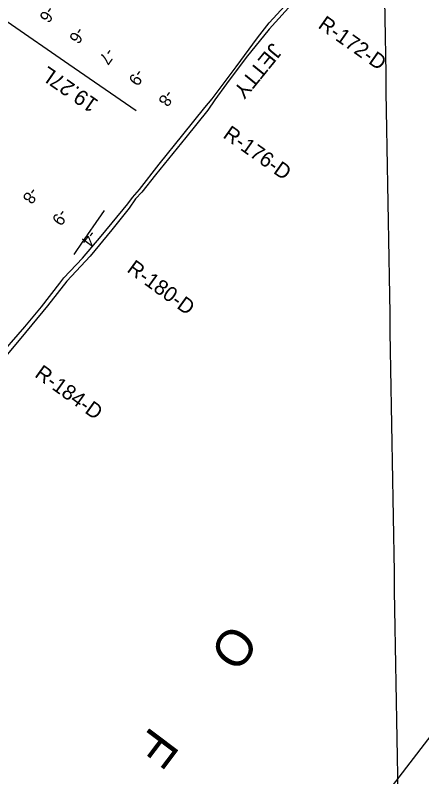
# Model space of a CAD drawing. Extents: x 3879599 to 3900814, y 146526 to 168888.
# Drawn here: x 3893070 to 3894188, y 154174 to 156266 of the extents above; entities that cross this region are included whole.
import ezdxf

# ---------------------------------------------------------------- set-up
doc = ezdxf.new("R2010")
doc.units = 0
for name, color, linetype in [('V-GRID-FRAM', 7, 'Continuous'), ('V-GRID-MAJR', 7, 'Continuous'), ('V-LEVE-TOET', 7, 'Continuous'), ('V-RIVR-IDEN', 7, 'Continuous'), ('V-RIVR-JETY', 7, 'Continuous'), ('V-RIVR-RANG', 7, 'Continuous'), ('V-RIVR-RANG-IDEN', 7, 'Continuous'), ('V-STRM-FMON', 7, 'Continuous'), ('V-TOPO-MINR', 7, 'Continuous')]:
    doc.layers.add(name, color=color, linetype=linetype)

msp = doc.modelspace()

# ---------------------------------------------------------------- linework, layer by layer
at = {"layer": 'V-GRID-FRAM'}
msp.add_lwpolyline([(3898776.6, 160226.4), (3889730.7, 148455.2), (3882888.9, 153284.4), (3891901.5, 165241.3), (3898776.6, 160226.4)], dxfattribs=at)
at = {"layer": 'V-GRID-MAJR'}
msp.add_spline([(3894134.7, 153416.7), (3894080.4, 156663.6), (3893979, 162723.9), (3893946.7, 164659.1)], degree=3, dxfattribs=at)
at = {"layer": 'V-LEVE-TOET'}
msp.add_lwpolyline([(3893403.2, 156002.9), (3893217.5, 156130.1), (3893048.4, 156247.9), (3892896.3, 156354.3)], dxfattribs=at)
at = {"layer": 'V-RIVR-JETY'}
for points in [[(3894117.3, 156651.7), (3894079.2, 156602.7), (3894043.1, 156551.8), (3894002.8, 156500.5), (3893956.5, 156444.6), (3893898.6, 156375.3), (3893839.2, 156305.5), (3893768.1, 156227.3), (3893705.7, 156149.9), (3893651.7, 156077.6), (3893618.9, 156033.2), (3893599.5, 156004.6)], [(3893611.6, 156035.8), (3893678, 156124.2), (3893736.5, 156203.8), (3893769, 156244.8), (3893811.6, 156291.5), (3893863.6, 156352.5), (3893892.8, 156383.2), (3893915.5, 156412.6), (3893955.9, 156461.3), (3894013.4, 156531), (3894060.3, 156596), (3894111.5, 156656.9), (3894119, 156666.1)], [(3893412.3, 155786.9), (3893466.4, 155856.6), (3893531.4, 155937.4), (3893591.8, 156012.4), (3893611.6, 156035.8)], [(3893599.5, 156004.6), (3893539.4, 155929.9), (3893455.8, 155827.2), (3893418.8, 155779.8), (3893401.2, 155761.7)], [(3893016.3, 155318.7), (3893097, 155409.6), (3893142.6, 155464.3), (3893193.3, 155529.8), (3893203.8, 155544.7), (3893255.4, 155598.4), (3893307, 155658.6), (3893380.2, 155747.8), (3893392.5, 155765), (3893412.3, 155786.9)], [(3893401.2, 155761.7), (3893383.4, 155735.7), (3893336, 155676), (3893276.6, 155604), (3893212.2, 155535.7), (3893158.9, 155467.2), (3893086, 155378.3), (3893009.8, 155289.4), (3892931, 155195.2), (3892859.8, 155101.4), (3892769.8, 154985), (3892723.9, 154932.9), (3892677.1, 154881.5), (3892656.9, 154860.4), (3892622.6, 154814.1), (3892534.6, 154695.5), (3892451.7, 154594.8), (3892385.6, 154513.6), (3892293.4, 154397.6), (3892219.9, 154301.1), (3892142.7, 154203.1), (3892063.5, 154110.7)]]:
    msp.add_lwpolyline(points, dxfattribs=at)
at = {"layer": 'V-TOPO-MINR'}
msp.add_lwpolyline([(3893232.9, 155608.3), (3893257.6, 155645.2), (3893260.7, 155649.8), (3893263.9, 155654.5), (3893267.1, 155659.1), (3893270.3, 155663.7), (3893293.4, 155696.7), (3893308, 155717.9), (3893315.6, 155729.1)], dxfattribs=at)

# ---------------------------------------------------------------- texts
at = {"layer": 'V-RIVR-IDEN'}
for s, p in [('O', (3893664, 154600)), ('F', (3893445.5, 154315.6))]:
    msp.add_text(s, height=100, rotation=232.9925, dxfattribs=at).set_placement(p)
at = {"layer": 'V-RIVR-JETY'}
msp.add_text('JETTY', height=42, rotation=230.9182, dxfattribs=at).set_placement((3893776, 156192.4))
at = {"layer": 'V-RIVR-RANG'}
for s, rotation, p in [('-6', 234.6583, (3893158.2, 156293.5)), ('-6', 234.6583, (3893239.9, 156235.8)), ('-7', 234.6583, (3893321.6, 156178.2)), ('-9', 234.6583, (3893403.2, 156120.4)), ('-8', 234.6583, (3893485.2, 156063.1)), ('-8', 233.7983, (3893112.4, 155795.6)), ('-9', 233.7983, (3893193.1, 155736.4)), ('-4', 233.7983, (3893273.9, 155677.6))]:
    msp.add_text(s, height=33.5, rotation=rotation, dxfattribs=at).set_placement(p)
at = {"layer": 'V-RIVR-RANG-IDEN'}
for s, rotation, p in [('R-172-D', 324.8648, (3893900.3, 156232.9)), ('R-176-D', 324.8046, (3893639, 155931.4)), ('R-180-D', 323.9387, (3893375, 155563)), ('R-184-D', 324.3276, (3893121.4, 155274.4))]:
    msp.add_text(s, height=41.5, rotation=rotation, dxfattribs=at).set_placement(p)
at = {"layer": 'V-STRM-FMON'}
msp.add_text('19.27L', height=42, rotation=145.4611, dxfattribs=at).set_placement((3893301.9, 156029.9))

doc.saveas('drawing.dxf')
